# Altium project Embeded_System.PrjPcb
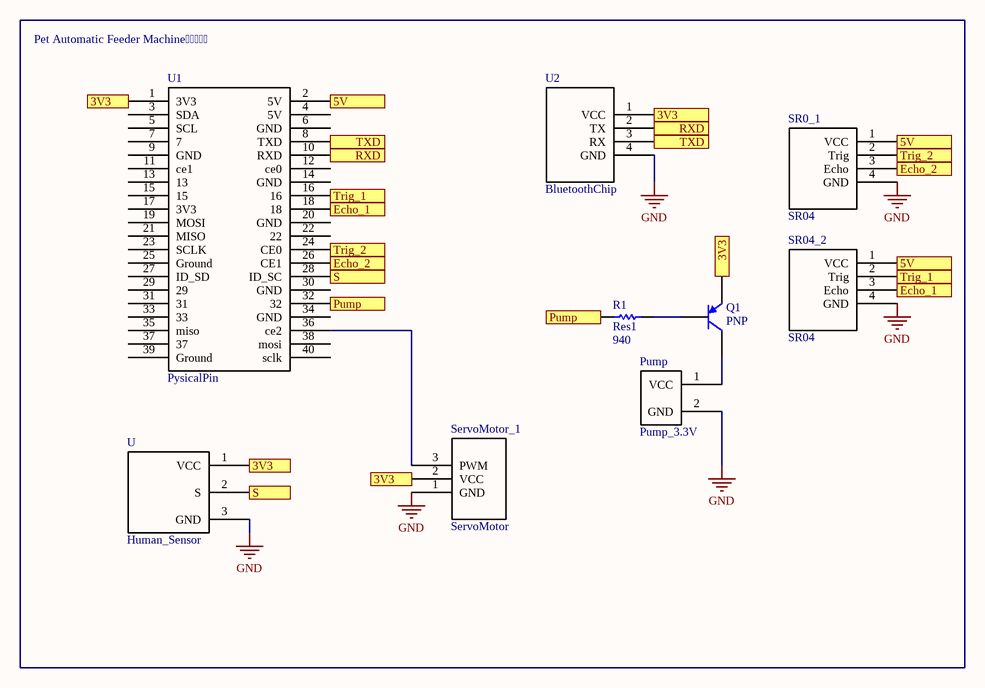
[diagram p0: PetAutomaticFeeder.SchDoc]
1 sheet, 9 parts. Net scope: flat (ports and power ports of the same name join across sheets).

## Sheet PetAutomaticFeeder.SchDoc
size A4; SheetNumber: 1; SheetTotal: 1

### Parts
Pump  Pump_3.3V
Q1  PNP  [SOT-23B_N]
R1  Res1  value 940  [AXIAL-0.3]
ServoMotor_1  ServoMotor
SR0_1  SR04
SR04_2  SR04
U  Human_Sensor
U1  PysicalPin
U2  BluetoothChip

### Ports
3V3, 5V, Echo_1, Echo_2, Pump, RXD, S, Trig_1, Trig_2, TXD

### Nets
GND: Pump.2(GND) ServoMotor_1.1(GND) SR0_1.4(GND) SR04_2.4(GND) U.3(GND) U2.4(GND)
NetPump_1: Pump.1(VCC) Q1.1(C)
NetQ1_2: Q1.2(B) R1.2
NetQ1_3: Q1.3(E) ServoMotor_1.2(VCC) U.1(VCC) U1.1(3V3) U2.1(VCC) ; port 3V3
NetR1_1: R1.1 U1.32 ; port Pump
NetServoMotor_1_3: ServoMotor_1.3(PWM) U1.36(ce2)
NetSR0_1_1: SR0_1.1(VCC) SR04_2.1(VCC) U1.2(5V) ; port 5V
NetSR0_1_2: SR0_1.2(Trig) U1.24(CE0) ; port Trig_2
NetSR0_1_3: SR0_1.3(Echo) U1.26(CE1) ; port Echo_2
NetSR04_2_2: SR04_2.2(Trig) U1.16 ; port Trig_1
NetSR04_2_3: SR04_2.3(Echo) U1.18 ; port Echo_1
NetU1_8: U1.8(TXD) U2.3(RX) ; port TXD
NetU1_10: U1.10(RXD) U2.2(TX) ; port RXD
NetU_2: U.2(S) U1.28(ID_SC) ; port S

Not connected (* = marked no-connect by the designer): U1 3(SDA) 4(5V) 5(SCL) 6(GND) 7 9(GND) 11(ce1) 12(ce0) 13 14(GND) 15 17(3V3) 19(MOSI) 20(GND) 21(MISO) 22 23(SCLK) 25(Ground) 27(ID_SD) 29 30(GND) 31 33 34(GND) 35(miso) 37 38(mosi) 39(Ground) 40(sclk)

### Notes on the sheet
- Pet Automatic Feeder Machine

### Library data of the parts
Pump = Pump
Q1 = PNP: PNP Bipolar Transistor
R1 = Res1: Resistor
U1 = RespberryPi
